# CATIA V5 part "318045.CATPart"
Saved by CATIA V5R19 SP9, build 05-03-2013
Part number: 318045
Source: Unknown
Bounding box of the stored display mesh (mm): x -4.4 to 267.6, y 93.501 to 140.001, z 435 to 559
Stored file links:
  D:\16-SIL\kale oto\R19_V1\318045.CATPart
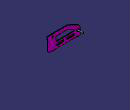
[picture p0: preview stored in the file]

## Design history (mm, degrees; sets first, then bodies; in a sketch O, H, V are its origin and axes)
Set1
  Line1: stored without definition
Body1 "120\\22\\MANIFOLD_SOLID_BREP #39330" (main body)
  Solid1: solid without history
Body2 "120\\106\\42\\MANIFOLD_SOLID_BREP #44818"
  Solid2: solid without history
Body3 "241\\220\\MANIFOLD_SOLID_BREP #154205"
  Solid3: solid without history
